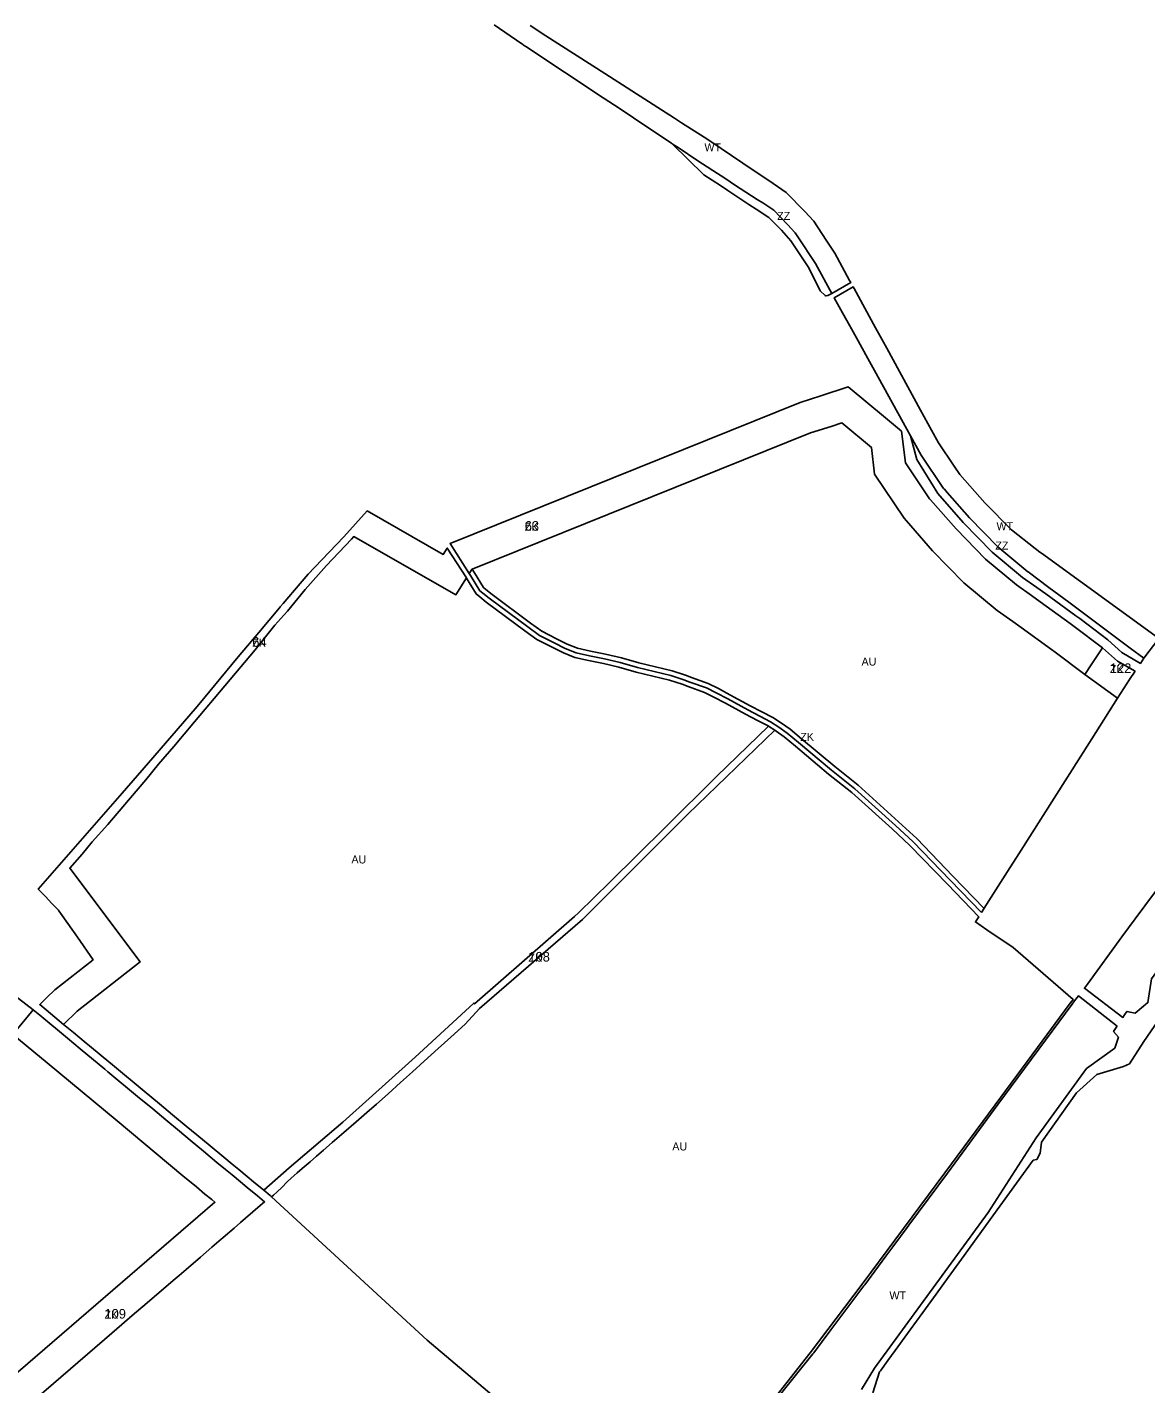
# Model space of a CAD drawing. Extents: x -537068 to -534056, y -1176840 to -1172401.
# Drawn here: x -536233 to -535534, y -1176344 to -1175496 of the extents above; entities that cross this region are included whole.
import ezdxf

# ---------------------------------------------------------------- set-up
doc = ezdxf.new("R2010")
doc.units = 0
for name, color, linetype in [('90550013', 7, 'Continuous'), ('90640013', 7, 'Continuous'), ('90670013', 7, 'Continuous'), ('90710013', 7, 'Continuous'), ('90710023', 7, 'Continuous'), ('90750013', 7, 'Continuous'), ('ID_navrh', 7, 'Continuous')]:
    doc.layers.add(name, color=color, linetype=linetype)

msp = doc.modelspace()

# ---------------------------------------------------------------- linework, layer by layer
at = {"layer": '90550013'}
msp.add_lwpolyline([(-535704.11, -1176349.3), (-535700.03, -1176336.26), (-535699.43, -1176335.44), (-535694.79, -1176329.04), (-535690.21, -1176322.74), (-535680.9, -1176309.93), (-535673.01, -1176299.08), (-535664.71, -1176287.65), (-535660.94, -1176282.47), (-535657.12, -1176277.22), (-535648.75, -1176265.71), (-535629.13, -1176238.73), (-535604.01, -1176203.9), (-535601.8, -1176203.42), (-535599.72, -1176199.54), (-535598.85, -1176192.74), (-535576.94, -1176161.89), (-535564.25, -1176150.34), (-535547.48, -1176145.43), (-535543.93, -1176143.64), (-535534.97, -1176129.73), (-535523.9, -1176113.7)], dxfattribs=at)
at = {"layer": '90640013'}
for points in [[(-535918.33, -1175494.77), (-535912.86, -1175498.4), (-535910.82, -1175499.75), (-535879.25, -1175519.97), (-535871.63, -1175524.85), (-535854.81, -1175535.62), (-535828.09, -1175552.76), (-535823.67, -1175555.59), (-535809.57, -1175564.63), (-535806.1, -1175566.86), (-535785.45, -1175580.79), (-535766.5, -1175593.57), (-535758.36, -1175599.06), (-535746.78, -1175611.09), (-535741.1, -1175617), (-535733.33, -1175628.97), (-535728.01, -1175637.17), (-535718.77, -1175654.08), (-535718.04, -1175655.42), (-535729.79, -1175662.18), (-535740.12, -1175643.46), (-535750.99, -1175626.84), (-535752.64, -1175624.31), (-535757.59, -1175619.11), (-535766.09, -1175610.17), (-535772.96, -1175605.71), (-535776.38, -1175603.48), (-535790.56, -1175594.27), (-535796.11, -1175590.67), (-535804.27, -1175585.37), (-535814.26, -1175578.87), (-535825.3, -1175571.52), (-535829.54, -1175568.69), (-535830.04, -1175568.35), (-535845.34, -1175558.14), (-535862.15, -1175546.92), (-535872.67, -1175539.97), (-535921.1, -1175507.99), (-535922.56, -1175507.02), (-535922.97, -1175506.73), (-535930.72, -1175501.34), (-535940.73, -1175494.38)], [(-535525.59, -1175877.78), (-535534.77, -1175890.22), (-535543.32, -1175883.85), (-535581.78, -1175855.19), (-535594.17, -1175845.96), (-535607.12, -1175836.31), (-535607.3, -1175836.17), (-535626.13, -1175820.65), (-535643.89, -1175802.53), (-535657.8, -1175786.6), (-535659.52, -1175784.63), (-535659.96, -1175784.13), (-535673.99, -1175763.31), (-535680.67, -1175751.2), (-535682.99, -1175747), (-535703.23, -1175710.32), (-535707.3, -1175702.86), (-535713.43, -1175691.84), (-535718.62, -1175682.43), (-535723.1, -1175674.31), (-535728.28, -1175664.92), (-535716.58, -1175658.08), (-535715.95, -1175659.24), (-535702.55, -1175683.75), (-535699.66, -1175689.03), (-535695.56, -1175696.43), (-535674.39, -1175735.25), (-535667.59, -1175747.69), (-535663.21, -1175755.7), (-535653.32, -1175770.27), (-535649.91, -1175775.29), (-535634.23, -1175793.2), (-535617.59, -1175809.94), (-535602.78, -1175821.58), (-535599.85, -1175823.87), (-535598.9, -1175824.62), (-535525.69, -1175877.72)], [(-535764.34, -1176353.29), (-535752.68, -1176338.75), (-535741.6, -1176324.94), (-535741.07, -1176324.23), (-535735.81, -1176317.18), (-535730.4, -1176309.95), (-535719.11, -1176294.83), (-535709.73, -1176282.34), (-535709.27, -1176281.73), (-535700.74, -1176270.21), (-535696.1, -1176263.94), (-535691.75, -1176258.07), (-535686.99, -1176251.65), (-535682.81, -1176246), (-535681.71, -1176244.51), (-535657.63, -1176212.04), (-535626.09, -1176169.01), (-535579.75, -1176106.46), (-535578.1, -1176104.22), (-535575.75, -1176101.2), (-535551.61, -1176120.18), (-535551.69, -1176120.31), (-535553.82, -1176123.5), (-535550.75, -1176127.07), (-535552.89, -1176133.89), (-535570.8, -1176146.67), (-535602.1, -1176189.88), (-535632.19, -1176236.64), (-535703.24, -1176333.84), (-535711.31, -1176347.15)]]:
    msp.add_lwpolyline(points, dxfattribs=at)
msp.add_lwpolyline([(-535455.23, -1175987.51), (-535530.06, -1176090.53), (-535532.28, -1176105.42), (-535540.24, -1176112.01), (-535545.43, -1176110.93), (-535546.85, -1176113.06), (-535547.96, -1176114.72), (-535572.04, -1176096.44), (-535570.1, -1176093.95), (-535548.55, -1176064.33), (-535540.25, -1176053.13), (-535521.49, -1176027.83), (-535483.92, -1175984.25), (-535463.75, -1175955.3), (-535446.09, -1175974.93), (-535445.68, -1175975.28), (-535446.65, -1175976.52), (-535451.76, -1175983.06)], close=True, dxfattribs=at)
at = {"layer": '90670013'}
for points in [[(-535729.79, -1175662.18), (-535732.42, -1175663.48), (-535733.47, -1175663.8), (-535734.04, -1175663.61), (-535737.19, -1175660.63), (-535744.24, -1175646.27), (-535755.43, -1175629.34), (-535761.28, -1175622.73), (-535769.15, -1175614.68), (-535777.12, -1175609.67), (-535781.75, -1175606.56), (-535794.85, -1175597.89), (-535799.42, -1175594.86), (-535809.76, -1175588.03), (-535829.54, -1175568.69), (-535825.3, -1175571.52), (-535814.26, -1175578.87), (-535804.27, -1175585.37), (-535796.11, -1175590.67), (-535790.56, -1175594.27), (-535776.38, -1175603.48), (-535772.96, -1175605.71), (-535766.09, -1175610.17), (-535757.59, -1175619.11), (-535752.64, -1175624.31), (-535750.99, -1175626.84), (-535740.12, -1175643.46)], [(-535557.47, -1175878.66), (-535574.85, -1175865.48), (-535577.41, -1175863.63), (-535596.16, -1175850.04), (-535601.63, -1175846.07), (-535610.74, -1175839.67), (-535629.65, -1175823.94), (-535647.82, -1175805.36), (-535663.64, -1175787.32), (-535676.62, -1175766.04), (-535680.67, -1175751.2), (-535673.99, -1175763.31), (-535659.96, -1175784.13), (-535659.52, -1175784.63), (-535657.8, -1175786.6), (-535643.89, -1175802.53), (-535626.13, -1175820.65), (-535607.3, -1175836.17), (-535607.12, -1175836.31), (-535594.17, -1175845.96), (-535581.78, -1175855.19), (-535543.32, -1175883.85), (-535534.77, -1175890.22), (-535537, -1175893.45), (-535548.52, -1175886.64)]]:
    msp.add_lwpolyline(points, close=True, dxfattribs=at)
at = {"layer": '90710013'}
msp.add_lwpolyline([(-535636.33, -1176049.12), (-535655.86, -1176028.92), (-535678.91, -1176005.05), (-535690.12, -1175994.66), (-535715.4, -1175971.76), (-535729.93, -1175960.24), (-535750.71, -1175942.84), (-535757.72, -1175936.96), (-535762.97, -1175933.33), (-535768.11, -1175929.95), (-535774.87, -1175926.44), (-535782.25, -1175922.56), (-535794.89, -1175915.67), (-535802.09, -1175911.79), (-535808.23, -1175908.79), (-535818.62, -1175905.16), (-535822.37, -1175903.66), (-535830.38, -1175901.03), (-535851.29, -1175896.02), (-535862.05, -1175892.89), (-535871.94, -1175890.51), (-535881.33, -1175888.64), (-535889.59, -1175886.88), (-535896.35, -1175884.13), (-535903.3, -1175880.69), (-535912.56, -1175875.93), (-535919.82, -1175870.67), (-535943.98, -1175852.77), (-535947.86, -1175849.64), (-535949.74, -1175848.02), (-535955.62, -1175838.5), (-535956.44, -1175837.23), (-535954.84, -1175834.66), (-535954.59, -1175834.56), (-535953.09, -1175836.9), (-535947.43, -1175846.05), (-535945.94, -1175847.34), (-535942.15, -1175850.4), (-535918.05, -1175868.25), (-535910.99, -1175873.37), (-535901.95, -1175878.01), (-535895.12, -1175881.39), (-535888.71, -1175884), (-535880.72, -1175885.7), (-535871.3, -1175887.58), (-535861.28, -1175889.99), (-535850.52, -1175893.12), (-535829.56, -1175898.14), (-535821.34, -1175900.84), (-535817.56, -1175902.35), (-535807.07, -1175906.02), (-535800.72, -1175909.13), (-535793.46, -1175913.04), (-535780.84, -1175919.91), (-535773.48, -1175923.78), (-535766.59, -1175927.35), (-535761.3, -1175930.84), (-535755.89, -1175934.57), (-535748.78, -1175940.54), (-535728.03, -1175957.91), (-535713.46, -1175969.47), (-535688.09, -1175992.45), (-535676.81, -1176002.91), (-535654.17, -1176026.34), (-535634.67, -1176046.52), (-535634.82, -1176046.75)], close=True, dxfattribs=at)
at = {"layer": '90710023'}
for points in [[(-535749.68, -1175730.47), (-535736.67, -1175726.21), (-535719.53, -1175720.59), (-535696.32, -1175739.98), (-535686.24, -1175748.4), (-535683.8, -1175768), (-535668.77, -1175790.56), (-535668.17, -1175791.26), (-535652.23, -1175809.44), (-535633.72, -1175828.36), (-535614.39, -1175844.44), (-535605.12, -1175850.96), (-535599.68, -1175854.9), (-535580.92, -1175868.49), (-535578.42, -1175870.31), (-535560.76, -1175883.69), (-535567.74, -1175894.34), (-535571.74, -1175900.46), (-535590.32, -1175886.38), (-535592.65, -1175884.69), (-535611.42, -1175871.09), (-535616.74, -1175867.23), (-535626.55, -1175860.34), (-535647.3, -1175843.08), (-535666.91, -1175823.04), (-535683.26, -1175804.38), (-535684.73, -1175802.68), (-535703.11, -1175775.1), (-535705.05, -1175758.49), (-535723.63, -1175743.14), (-535730.27, -1175745.43), (-535743.13, -1175749.36), (-535954.59, -1175834.56), (-535954.84, -1175834.66), (-535956.44, -1175837.23), (-535968.39, -1175818.56)], [(-536209.85, -1176119.04), (-536220.8, -1176109.96), (-536224.78, -1176106.66), (-536220.36, -1176102.28), (-536215.38, -1176097.36), (-536191.39, -1176078.65), (-536201.26, -1176064.62), (-536210.85, -1176050.98), (-536212.9, -1176048.06), (-536213.13, -1176047.73), (-536217.36, -1176043.27), (-536221.04, -1176039.38), (-536225.71, -1176034.45), (-536173.33, -1175974.59), (-536156.87, -1175955.6), (-536127.54, -1175921.77), (-536125.4, -1175919.17), (-536104.79, -1175894.1), (-536100.8, -1175889.37), (-536087.89, -1175874.08), (-536074.99, -1175858.81), (-536074.44, -1175858.16), (-536072.6, -1175856.08), (-536062.03, -1175843.57), (-536057.11, -1175837.75), (-536048.52, -1175828.8), (-536034.67, -1175814.36), (-536020.26, -1175798.17), (-535972.61, -1175825.36), (-535970.14, -1175821.39), (-535958.19, -1175840.06), (-535964.71, -1175850.59), (-536028.51, -1175814.18), (-536029.96, -1175815.7), (-536045.61, -1175832.23), (-536058.92, -1175847.3), (-536069.91, -1175860.71), (-536072.33, -1175863.39), (-536077.89, -1175869.53), (-536090.05, -1175884.93), (-536128.05, -1175929.98), (-536141, -1175945.46), (-536150.55, -1175956.45), (-536158.53, -1175966.22), (-536172.83, -1175983), (-536182.22, -1175994.02), (-536191.93, -1176005.04), (-536198.3, -1176012.68), (-536206.01, -1176021.47), (-536162.05, -1176080.03), (-536201.47, -1176110.75)], [(-535540.36, -1175898.34), (-535543.85, -1175903.41), (-535551.3, -1175915.16), (-535571.74, -1175900.46), (-535567.74, -1175894.34), (-535560.76, -1175883.69), (-535551.25, -1175892.1)], [(-536079.97, -1176226.81), (-536080.82, -1176226.03), (-536084.8, -1176222.72), (-536068.94, -1176208.75), (-536035.32, -1176180.12), (-535990.19, -1176139.56), (-535953.55, -1176105.76), (-535953.02, -1176106.27), (-535890.69, -1176051.7), (-535888.17, -1176049.31), (-535868.53, -1176030.23), (-535833.82, -1175995.83), (-535801.98, -1175964.04), (-535769.33, -1175932.73), (-535765.54, -1175935.22), (-535819.83, -1175987.56), (-535885.65, -1176053.5), (-535950.04, -1176109.13), (-535958.85, -1176118.83), (-535967.89, -1176126.99), (-535975.82, -1176134.14), (-535984.5, -1176141.98), (-535991.83, -1176148.6), (-535999.3, -1176155.34), (-536007.11, -1176162.38), (-536014.42, -1176168.97), (-536020.29, -1176174.05), (-536027.08, -1176179.93), (-536034.79, -1176186.61), (-536041.99, -1176192.85), (-536047.47, -1176197.6), (-536051.82, -1176201.37), (-536055.87, -1176204.87), (-536060.8, -1176209.15), (-536063.89, -1176211.83), (-536067.68, -1176215.11), (-536070.14, -1176217.53), (-536073.58, -1176220.9), (-536076.32, -1176223.58), (-536078.6, -1176225.82)]]:
    msp.add_lwpolyline(points, close=True, dxfattribs=at)
msp.add_lwpolyline([(-536242.72, -1176340.22), (-536115.28, -1176230.23), (-536117.33, -1176228.53), (-536121.5, -1176225.06), (-536126.8, -1176220.65), (-536135.26, -1176213.62), (-536176.47, -1176179.39), (-536220.12, -1176143.12), (-536241.61, -1176125.27), (-536228.83, -1176109.89), (-536224.79, -1176113.24), (-536207.34, -1176127.74), (-536199.44, -1176134.3), (-536184.13, -1176147.02), (-536182.22, -1176148.61), (-536163.69, -1176164.01), (-536154.18, -1176171.91), (-536146.04, -1176178.67), (-536137.48, -1176185.78), (-536130.74, -1176191.38), (-536122.48, -1176198.24), (-536114.02, -1176205.27), (-536108.71, -1176209.68), (-536104.54, -1176213.15), (-536099.27, -1176217.53), (-536095.13, -1176220.97), (-536088.79, -1176226.24), (-536084.31, -1176229.96), (-536088.44, -1176233.51), (-536099.25, -1176242.81), (-536103.33, -1176246.32), (-536110.08, -1176252.13), (-536110.32, -1176252.33), (-536111.34, -1176253.21), (-536117.25, -1176258.29), (-536124.4, -1176264.44), (-536133.32, -1176272.11), (-536137.68, -1176275.86), (-536140.18, -1176278.01), (-536160.25, -1176295.27), (-536165.46, -1176299.75), (-536179.68, -1176311.98), (-536226.88, -1176352.57)], dxfattribs=at)
at = {"layer": '90750013'}
for points in [[(-535571.74, -1175900.46), (-535551.3, -1175915.16), (-535567.39, -1175940.55), (-535612.97, -1176012.45), (-535619.96, -1176023.48), (-535634.6, -1176046.41), (-535634.67, -1176046.52), (-535654.17, -1176026.34), (-535676.81, -1176002.91), (-535688.09, -1175992.45), (-535713.46, -1175969.47), (-535728.03, -1175957.91), (-535748.78, -1175940.54), (-535755.89, -1175934.57), (-535761.3, -1175930.84), (-535766.59, -1175927.35), (-535773.48, -1175923.78), (-535780.84, -1175919.91), (-535793.46, -1175913.04), (-535800.72, -1175909.13), (-535807.07, -1175906.02), (-535817.56, -1175902.35), (-535821.34, -1175900.84), (-535829.56, -1175898.14), (-535850.52, -1175893.12), (-535861.28, -1175889.99), (-535871.3, -1175887.58), (-535880.72, -1175885.7), (-535888.71, -1175884), (-535895.12, -1175881.39), (-535901.95, -1175878.01), (-535910.99, -1175873.37), (-535918.05, -1175868.25), (-535942.15, -1175850.4), (-535945.94, -1175847.34), (-535947.43, -1175846.05), (-535953.09, -1175836.9), (-535954.59, -1175834.56), (-535743.13, -1175749.36), (-535730.27, -1175745.43), (-535723.63, -1175743.14), (-535705.05, -1175758.49), (-535703.11, -1175775.1), (-535684.73, -1175802.68), (-535683.26, -1175804.38), (-535666.91, -1175823.04), (-535647.3, -1175843.08), (-535626.55, -1175860.34), (-535616.74, -1175867.23), (-535611.42, -1175871.09), (-535592.65, -1175884.69), (-535590.32, -1175886.38)], [(-536209.85, -1176119.04), (-536201.47, -1176110.75), (-536162.05, -1176080.03), (-536206.01, -1176021.47), (-536198.3, -1176012.68), (-536191.93, -1176005.04), (-536182.22, -1175994.02), (-536172.83, -1175983), (-536158.53, -1175966.22), (-536150.55, -1175956.45), (-536141, -1175945.46), (-536128.05, -1175929.98), (-536090.05, -1175884.93), (-536077.89, -1175869.53), (-536072.33, -1175863.39), (-536069.91, -1175860.71), (-536058.92, -1175847.3), (-536045.61, -1175832.23), (-536029.96, -1175815.7), (-536028.51, -1175814.18), (-535964.71, -1175850.59), (-535958.19, -1175840.06), (-535958.16, -1175840.1), (-535952.05, -1175849.98), (-535949.79, -1175851.94), (-535945.82, -1175855.15), (-535921.6, -1175873.09), (-535914.14, -1175878.49), (-535904.65, -1175883.37), (-535897.59, -1175886.87), (-535890.48, -1175889.76), (-535881.94, -1175891.57), (-535872.59, -1175893.44), (-535862.82, -1175895.79), (-535852.06, -1175898.92), (-535831.2, -1175903.92), (-535823.4, -1175906.48), (-535819.67, -1175907.97), (-535809.38, -1175911.56), (-535803.46, -1175914.46), (-535796.32, -1175918.31), (-535783.67, -1175925.2), (-535776.25, -1175929.1), (-535769.62, -1175932.54), (-535769.33, -1175932.73), (-535801.98, -1175964.04), (-535833.82, -1175995.83), (-535868.53, -1176030.23), (-535888.17, -1176049.31), (-535890.69, -1176051.7), (-535953.02, -1176106.27), (-535953.55, -1176105.76), (-535990.19, -1176139.56), (-536035.32, -1176180.12), (-536068.94, -1176208.75), (-536084.8, -1176222.72), (-536091.15, -1176217.46), (-536095.19, -1176214.11), (-536100.41, -1176209.78), (-536104.56, -1176206.34), (-536109.82, -1176201.98), (-536118.23, -1176195), (-536126.54, -1176188.11), (-536133.19, -1176182.6), (-536141.8, -1176175.46), (-536149.92, -1176168.73), (-536159.43, -1176160.85), (-536178.09, -1176145.38), (-536186.34, -1176138.53), (-536193.73, -1176132.4), (-536195.8, -1176130.69), (-536203.69, -1176124.15)]]:
    msp.add_lwpolyline(points, close=True, dxfattribs=at)
for points in [[(-535850.75, -1176427.84), (-535982.72, -1176316.41), (-536011.45, -1176289.95), (-536079.97, -1176226.81), (-536078.6, -1176225.82), (-536076.32, -1176223.58), (-536073.58, -1176220.9), (-536070.14, -1176217.53), (-536067.68, -1176215.11), (-536063.89, -1176211.83), (-536060.8, -1176209.15), (-536055.87, -1176204.87), (-536051.82, -1176201.37), (-536047.47, -1176197.6), (-536041.99, -1176192.85), (-536034.79, -1176186.61), (-536027.08, -1176179.93), (-536020.29, -1176174.05), (-536014.42, -1176168.97), (-536007.11, -1176162.38), (-535999.3, -1176155.34), (-535991.83, -1176148.6), (-535984.5, -1176141.98), (-535975.82, -1176134.14), (-535967.89, -1176126.99), (-535958.85, -1176118.83), (-535950.04, -1176109.13), (-535885.65, -1176053.5), (-535819.83, -1175987.56), (-535765.54, -1175935.22), (-535764.65, -1175935.81), (-535759.54, -1175939.34), (-535752.63, -1175945.14), (-535731.82, -1175962.56), (-535717.35, -1175974.04), (-535692.15, -1175996.87), (-535681.02, -1176007.2), (-535657.54, -1176031.49), (-535637.99, -1176051.72), (-535640.1, -1176055.04), (-535632.96, -1176059.86), (-535624.54, -1176065.54), (-535622.89, -1176066.65), (-535616.5, -1176070.96), (-535579.07, -1176103.38), (-535579.75, -1176104.28), (-535579.87, -1176104.45), (-535581.49, -1176106.71), (-535601.29, -1176133.46), (-535627.85, -1176169.35), (-535659.3, -1176211.77), (-535710.77, -1176281.42), (-535743.34, -1176324.33), (-535784.04, -1176376)], [(-536308.86, -1176048.3), (-536228.83, -1176109.89), (-536241.61, -1176125.27), (-536220.12, -1176143.12), (-536176.47, -1176179.39), (-536135.26, -1176213.62), (-536126.8, -1176220.65), (-536121.5, -1176225.06), (-536117.33, -1176228.53), (-536115.28, -1176230.23), (-536242.72, -1176340.22)]]:
    msp.add_lwpolyline(points, dxfattribs=at)

# ---------------------------------------------------------------- texts
at = {"layer": '90640013'}
for rotation, p in [(360, (-535809.44, -1175573.4)), (360, (-535626.93, -1175810.18)), (0, (-535693.83, -1176290.92))]:
    msp.add_text('WT', height=5, rotation=rotation, dxfattribs=at).set_placement(p)
at = {"layer": '90670013'}
for rotation, p in [(360, (-535763.97, -1175616.24)), (0, (-535627.66, -1175822.32))]:
    msp.add_text('ZZ', height=5, rotation=rotation, dxfattribs=at).set_placement(p)
at = {"layer": '90710013'}
msp.add_text('ZK', height=5, rotation=360, dxfattribs=at).set_placement((-535749.56, -1175941.84))
at = {"layer": '90710023'}
for rotation, p in [(360, (-535921.69, -1175810.52)), (0, (-536091.95, -1175883.04)), (0, (-535556.09, -1175899.43)), (360, (-535919.4, -1176079.77)), (0, (-536184.28, -1176302.88))]:
    msp.add_text('ZK', height=5, rotation=rotation, dxfattribs=at).set_placement(p)
at = {"layer": '90750013'}
for p in [(-535711.27, -1175894.83), (-535829.52, -1176197.81)]:
    msp.add_text('AU', height=5, rotation=0, dxfattribs=at).set_placement(p)
msp.add_text('AU', height=5, dxfattribs=at).set_placement((-536030, -1176018.45))
at = {"layer": 'ID_navrh'}
for s, rotation, p in [('63', 360, (-535921.69, -1175810.52)), ('122', 0, (-535556.09, -1175899.43)), ('108', 360, (-535919.4, -1176079.77)), ('109', 0, (-536184.28, -1176302.88))]:
    msp.add_text(s, height=6, rotation=rotation, dxfattribs=at).set_placement(p)
msp.add_text('64', height=6, dxfattribs=at).set_placement((-536091.95, -1175883.04))

doc.saveas('drawing.dxf')
